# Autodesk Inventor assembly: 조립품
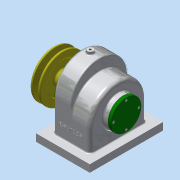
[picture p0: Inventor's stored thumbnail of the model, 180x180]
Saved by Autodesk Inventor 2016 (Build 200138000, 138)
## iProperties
Created: 2017-11
Part Number: 조립품
Material: 일반
Document SubType Name: Assembly
Designer: 605-15
Author: 605-15
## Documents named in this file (14)
- C:\Users\605-15\Desktop\471107V1019\조립품.iam
- C:\Users\605-15\Desktop\471107V1019\본체.ipt
- C:\Users\605-15\Desktop\471107V1019\뒤커버.ipt
- C:\Users\605-15\Desktop\471107V1019\베어링 6002.ipt
- C:\Users\605-15\Desktop\471107V1019\볼트 M3 x 8.ipt
- C:\Users\605-15\Desktop\471107V1019\앞커버.ipt
- C:\Users\605-15\Desktop\471107V1019\오일 실 15 30 7.ipt
- C:\Users\605-15\Desktop\471107V1019\축.ipt
- C:\Users\605-15\Desktop\471107V1019\키 - 5 x 5 x 18.ipt
- C:\Users\605-15\Desktop\471107V1019\키 - 6 x 6 x 22.ipt
- C:\Users\605-15\Desktop\471107V1019\스퍼기어.ipt
- C:\Users\605-15\Desktop\471107V1019\V-벨트풀리.ipt
- C:\Users\605-15\Desktop\471107V1019\멈춤나사 - M4 x 10.ipt
- 멈춤나사 - M4 x 10.ipt
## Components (1 placed, 1 different names)
1. V-벨트풀리:1 — 플러쉬:1
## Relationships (1: Flush 1)
- 플러쉬:1 [Flush]: V-벨트풀리:1
